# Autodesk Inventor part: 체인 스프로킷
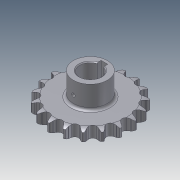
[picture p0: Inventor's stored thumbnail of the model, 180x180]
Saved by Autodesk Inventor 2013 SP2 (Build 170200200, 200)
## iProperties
Created: 2014-07
Part Number: 체인 스프로킷
Material: 강
Document SubType Name: Modeling
Designer: KYOUNG IL JANG
Density: 7.85 g/cm^3
Mass: 738.626 g
Surface Area: 236.854 cm^2
Volume: 94.0925 cm^3
CustomPartVersion: 1
Company: 한국ATC센터
Author: KYOUNG IL JANG
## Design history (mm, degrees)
sketch "이론적 톱니 프로파일"
  geometry: L1 (0, 0)-(0, 45.567); L2 (0, 0)-(14.795, 43.098); L3 (0, 45.567)-(14.795, 43.098); L4 (0, 45.567)-(5.661, 50.015); L5 (5.661, 50.015)-(-5.141, 45.406); L6 (-12.428, 43.493)-(-5.573, 46.417); L7 (-5.141, 45.406)-(-5.573, 46.417); L8 (5.573, 46.417)-(5.141, 45.406); L9 (0, 0)-(8.138, 48.771); A1 r 45.567 centre (0, 0) between (0, 45.567) and (14.795, 43.098); A2 r 49.445 centre (0, 0) between (7.302, 48.903) and (-7.302, 48.903); A3 r 4.545 centre (0, 45.567) between (-3.574, 42.758) and (3.574, 42.758); A4 r 7.453 centre (12.428, 43.493) between (7.302, 48.903) and (5.573, 46.417); A5 r 7.453 centre (-12.428, 43.493) between (-5.573, 46.417) and (-7.302, 48.903); A6 r 11.745 centre (5.661, 50.015) between (-5.141, 45.406) and (-3.574, 42.758); A7 r 11.745 centre (-5.661, 50.015) between (3.574, 42.758) and (5.141, 45.406); 2 further points
  constraints: 18 end point, 15 point on circle, 7 centre point, 3 coincident, 3 point on line, 3 symmetric about line, 3 tangent, 1 equal radius, 1 midpoint, 1 parallel, 1 vertical, 1 other
  dimensions: "d0" = 91.13301 diameter of A1 (computed from da_p, da_z); "d2" = 18.9474 deg angle of L2 L1 (computed from da_z); "d3" = 4.545 radius of A3 (= 0.5 x da_Dr + da_SC); "d10" = 128.158 deg angle of L4 L1 (computed from da_z); "d11" = 15.0526 deg angle of L5 L4 (computed from da_z); "d12" = 7.2 distance of L3.start L4.end (= 0.8 x da_Dr); "d13" = 11.745 distance of L4.end L5.end (= 1.3 x da_Dr + da_SC); "d14" = 12.6 distance of A4.centre L1.end (= 1.4 x da_Dr); "d23" = 4.5 distance from line of L9.end L3 (= da_Ha)
sketch "톱니 프로파일"
  geometry: L1 (0, 0)-(0, 45.567); L2 (0, 45.567)-(4.203, 43.837); L3 (0, 45.567)-(-4.203, 43.837); A1 r 4.545 centre (0, 45.567) between (-4.203, 43.837) and (4.203, 43.837); A2 r 22.68 centre (25.176, 35.206) between (7.12, 48.93) and (4.203, 43.837); A3 r 22.68 centre (-25.176, 35.206) between (-4.203, 43.837) and (-7.12, 48.93); A4 r 49.445 centre (0, 0) between (-7.12, 48.93) and (7.12, 48.93) reference; 1 further point
  constraints: 9 point on circle, 6 end point, 3 centre point, 2 tangent, 1 coincident, 1 equal radius, 1 vertical, 1 other
  dimensions: "d44" = 135.263 deg angle of L3 L2 (= da_Alfa); "d45" = 22.68 radius of A2 (= da_Re); "d46" = 4.545 radius of A1 (= da_Ri)
sketch "단면 프로파일"
  geometry: L1 (49.445, 0)-(-49.445, 0) reference; L2 (33.265, 6.65)-(-33.265, 6.65); L3 (-33.265, 6.65)-(-33.265, -6.65); L4 (-33.265, -6.65)-(33.265, -6.65); L5 (33.265, -6.65)-(33.265, 6.65); L6 (33.265, 6.65)-(49.445, 6.65); L7 (49.445, 6.65)-(49.445, -6.65); L8 (49.445, -6.65)-(33.265, -6.65); L9 (33.265, -6.65)-(33.265, 6.65); L10 (42.183, 6.65)-(0, 6.65); L11 (0, 6.65)-(0, -6.65); L12 (0, -6.65)-(42.183, -6.65); L13 (0, 6.65)-(0, -6.65); L14 (49.445, 4.775)-(49.445, -4.775); A1 r 15 centre (42.183, -8.35) between (49.445, 4.775) and (42.183, 6.65); A2 r 15 centre (42.183, 8.35) between (42.183, -6.65) and (49.445, -4.775); 2 further points
  constraints: 26 end point, 7 midpoint, 5 perpendicular, 4 parallel, 4 point on circle, 3 point on line, 3 symmetric about line, 2 centre point, 2 horizontal, 2 tangent, 1 collinear, 1 other
  dimensions: "d30" = 13.3 distance between parallel lines of L8 L6 (= da_Bf); "d31" = 66.53007 distance between parallel lines of L3 L5 (= da_Ds); "d32" = 13.3 distance between parallel lines of L4 L2 (= da_Bs); "d33" = 1.875 distance from line of L14.start L6 (= da_Ba); "d34" = 15 radius of A1 (= da_Rx); "d43" = 6.65 distance between parallel lines of L4 L1 (computed from da_k, da_pt, da_Bs)
revolve "슈라우드" stored, may be unused: angle "d36" = 90 deg
revolve "스트랜드" stored, may be unused: angle "d37" = 90 deg
extrude "이론적 톱니" cut sketch "이론적 톱니 프로파일" stored distance "d18" = 10; taper "d19" = 0 deg; dims "d49" = 0, "form_type" = 0 [user parameter]
extrude "톱니" cut sketch "톱니 프로파일" stored distance "d47" = 10; taper "d48" = 0 deg; dims "d50" = 10, "form_type" = 0 [user parameter]
node "타이밍 평면"
node "작업 평면3"
sketch "스케치5"
  geometry: C1 r 20 at (0, -45.567); 1 further point
  constraints: 1 centre point, 1 coincident
  dimensions: "d52" = 40 diameter of C1
extrude "돌출4" join sketch "스케치5" stored distance "d53" = 10; taper "d54" = 0 deg
sketch "스케치6"
  geometry: L1 (4, 11.843)-(4, 16.5); L2 (4, 16.5)-(-4, 16.5); L3 (-4, 16.5)-(-4, 11.843); A1 r 12.5 centre (0, 0) between (4, 11.843) and (-4, 11.843); 1 further point
  constraints: 6 end point, 2 parallel, 2 point on circle, 1 centre point, 1 coincident, 1 perpendicular, 1 vertical
  dimensions: "d55" = 25 diameter of A1; "d56" = 29 dimension on A1 L2 (computed from d55); "d57" = 8 distance of L1.end L2.end
extrude "돌출5" cut sketch "스케치6" stored distance "d58" = 10; taper "d59" = 0 deg
fillet "모깎기2" dims "d60" = 3
chamfer "모따기1" distance "d61" = 1; stored, may be unused: second distance "d62" = 2, angle "d63" = 45 deg
node "작업 평면4"
sketch "스케치7"
  geometry: L1 (-13.5, -13.3)-(13.5, -13.3) reference; 4 further points
  constraints: 1 vertical alignment
  dimensions: "d65" = 25 distance from line of point (0, 11.7) L1
hole "구멍1" sketch "스케치7" at (0, 11.7) diameter "d66" = 4.134; stored, may be unused: countersink angle "d70" = 90 deg, drill point angle "d72" = 118 deg; dims "d67" = 6, "d68" = 4, "d69" = 2, "d71" = 8
body "Solid1"
pattern_linear "스트랜드 패턴" dims "d40" = 24 (= da_pt)
pattern_circular "톱니 패턴" dims angle "d21" = 360 deg
other parameters: "da_p" = 15 [user parameter; used in 1 equation term], "da_Dr" = 9 [user parameter; used in 4 equation terms], "da_SC" = 0.045 [user parameter; used in 2 equation terms], "da_Ha" = 4.5 [user parameter; used in 1 equation term], "da_pt" = 24 [user parameter; used in 2 equation terms], "da_Bf" = 13.3 [user parameter; used in 1 equation term], "d28" = 0, "d29" = 0, "da_Ba" = 1.875 [user parameter; used in 1 equation term], "da_Rx" = 15 [user parameter; used in 1 equation term], "da_Ra" = 0.6 [user parameter], "da_Bs" = 13.3 [user parameter; used in 2 equation terms], "da_Ds" = 66.53007 [user parameter; used in 1 equation term], "d42" = 0, "da_Re" = 22.68 [user parameter; used in 1 equation term], "da_Ri" = 4.545 [user parameter; used in 1 equation term], "da_Alfa" = 135.263 deg [user parameter; used in 1 equation term]
